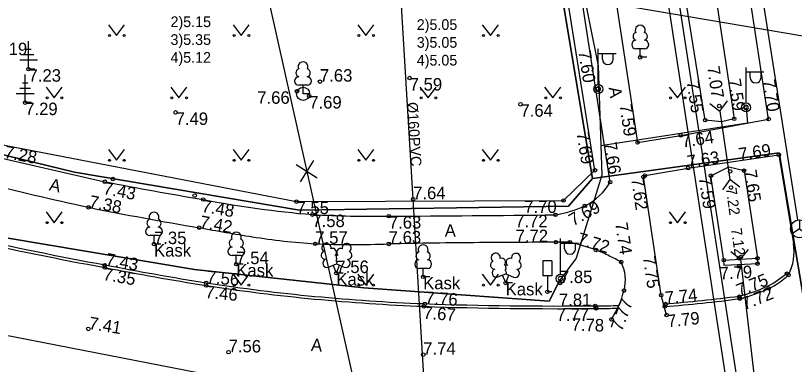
# Model space of a CAD drawing. Extents: x 473307 to 473719, y 6532843 to 6533381.
# Drawn here: x 473621.77 to 473665.5, y 6532915.94 to 6532935.52 of the extents above; entities that cross this region are included whole.
import ezdxf

# ---------------------------------------------------------------- set-up
doc = ezdxf.new("R2010")
doc.units = 0
for name, color, linetype in [('AED', 7, 'Continuous'), ('Default', 7, 'Continuous'), ('HALJASTUS', 7, 'Continuous'), ('KKAEV_NR', 7, 'Continuous'), ('KORGUS', 7, 'Continuous'), ('KTRASS', 7, 'Continuous'), ('KTRASS_TEKST', 7, 'Continuous'), ('LIIKLUS', 7, 'Continuous'), ('MPKAABEL', 7, 'Continuous'), ('PIIR', 7, 'Continuous'), ('POST', 7, 'Continuous'), ('PUU', 7, 'Continuous'), ('RAJATIS', 7, 'Continuous'), ('SIKAEV', 7, 'Continuous'), ('SITRASS', 7, 'Continuous'), ('TEE', 7, 'Continuous'), ('TRUUP', 7, 'Continuous'), ('TTRASS', 7, 'Continuous'), ('VEEKOGU', 7, 'Continuous'), ('VTRASS', 7, 'Continuous')]:
    doc.layers.add(name, color=color, linetype=linetype)

# ---------------------------------------------------------------- blocks, each defined once
blk = doc.blocks.new('SIKAEV')
at = {"layer": 'Default'}
for p, q in [((0, 1), (0, 0)), ((0, 0), (-0.83, -0.55)), ((0, 0), (0.83, -0.55))]:
    blk.add_line(p, q, dxfattribs=at)
blk.add_circle((0, 0), 1, dxfattribs=at)
blk = doc.blocks.new('LEHTP1')
at = {"layer": 'Default'}
for p, q in [((0.48, 0.95), (-0.48, 0.95)), ((0, 0), (0, 0.95)), ((0.76, 0), (0, 0))]:
    blk.add_line(p, q, dxfattribs=at)
for centre, radius, start, end in [((0, 3.04), 0.554, 332.5799, 207.4201), ((-0.34, 2.345), 0.465, 109.02174, 253.14154), ((0.34, 2.345), 0.465, 286.85082, 70.98591), ((-0.475, 1.425), 0.475, 90.0016, 269.3953), ((0.475, 1.425), 0.475, 270.6047, 89.9984)]:
    blk.add_arc(centre, radius, start, end, dxfattribs=at)
blk = doc.blocks.new('LEHTP2')
at = {"layer": 'Default'}
for p, q in [((-0.88, 0.67), (0.01, 1.02)), ((0, 0), (-0.35, 0.88)), ((0, 0), (0.36, 0.88)), ((0.01, 1.02), (0.89, 0.66)), ((0.76, 0), (0, 0))]:
    blk.add_line(p, q, dxfattribs=at)
blk.add_lwpolyline([(0.01, 2.01), (-0.03, 1.86), (-0.03, 1.82), (-0.01, 1.76), (0.03, 1.69), (0.04, 1.65), (0.01, 1.58), (-0.04, 1.48), (-0.05, 1.43), (-0.04, 1.4), (-0.02, 1.34), (0.05, 1.22), (0.06, 1.18), (0.05, 1.14), (0.02, 1.07), (0.01, 1.02)], dxfattribs=at)
for centre, radius, start, end in [((-1.114, 2.828), 0.512, 111.50269, 232.51731), ((-1.114, 2.828), 0.512, 350.48556, 111.50017), ((-0.445, 2.327), 0.448, 308.50412, 111.57247), ((0.481, 2.318), 0.45, 67.7016, 230.51262), ((1.158, 2.811), 0.512, 67.6168, 188.63142), ((1.158, 2.811), 0.512, 306.59966, 67.61428), ((-1.262, 2.005), 0.448, 111.43041, 274.49868), ((0.008, 1.535), 0.475, 66.76552, 111.50149), ((1.293, 1.986), 0.448, 264.6183, 67.68657), ((-1.053, 1.117), 0.475, 111.50143, 291.50036), ((1.07, 1.101), 0.475, 247.61661, 67.61554)]:
    blk.add_arc(centre, radius, start, end, dxfattribs=at)
blk = doc.blocks.new('LIIKLM')
at = {"layer": 'Default'}
for points in [[(-0.5, 3.5), (-0.5, 1.8)], [(0.5, 3.5), (-0.5, 3.5)], [(0.5, 3.5), (0.5, 1.8)], [(0.5, 1.8), (-0.5, 1.8)], [(0, 1.8), (0, 0)], [(0.5, 0), (0, 0)]]:
    blk.add_lwpolyline(points, dxfattribs=at)
blk = doc.blocks.new('MEPOST')
at = {"layer": 'Default'}
blk.add_circle((0, 0), 0.5, dxfattribs=at)
for start, end in [(0, 180), (180, 0)]:
    blk.add_arc((0, 0), 0.25, start, end, dxfattribs=at)
blk = doc.blocks.new('VAPOST')
at = {"layer": 'Default'}
for p, q in [((0, 0.5), (0, 4.5)), ((0, 4), (2, 4)), ((0.453, 3.358), (0.453, 4)), ((1.679, 3.358), (1.679, 4))]:
    blk.add_line(p, q, dxfattribs=at)
blk.add_arc((1.066, 3.358), 0.613, 180, 0, dxfattribs=at)
blk = doc.blocks.new('OKASP1')
at = {"layer": 'Default'}
for p, q in [((0, 0), (0, 3.15)), ((0.3, 2.2), (-0.3, 2.2)), ((1, 1), (-1, 1)), ((0.6, 1.6), (-0.6, 1.6)), ((0.72, 0), (0, 0))]:
    blk.add_line(p, q, dxfattribs=at)
blk = doc.blocks.new('MURU')
at = {"layer": 'Default'}
for p, q in [((-0.927, 1.213), (0, 0)), ((0, 0), (0.891, 1.213))]:
    blk.add_line(p, q, dxfattribs=at)
for centre in [(-0.802, 0), (0.856, 0)]:
    blk.add_circle(centre, 0.11, dxfattribs=at)
blk = doc.blocks.new('EITOOT')
at = {"layer": 'Default'}
for p, q in [((-0.99, 0.99), (0.99, -0.99)), ((-0.99, -0.99), (0.99, 0.99))]:
    blk.add_line(p, q, dxfattribs=at)
blk = doc.blocks.new('TORVAL')
at = {"layer": 'Default'}
blk.add_lwpolyline([(-1, -1), (0, 0), (-1, 1)], dxfattribs=at)

msp = doc.modelspace()

# ---------------------------------------------------------------- linework, layer by layer
at = {"layer": 'AED'}
msp.add_lwpolyline([(473550.051, 6532959.211), (473554.174, 6532956.453), (473573.719, 6532945.513), (473580.254, 6532941.8), (473591.86, 6532937.524), (473605.919, 6532932.298), (473608.286, 6532931.42), (473621.231, 6532928.229), (473637.541, 6532925.082), (473652.528, 6532925.143), (473654.3, 6532926.84), (473651.933, 6532941.676), (473648.983, 6532959.55), (473630.652, 6532956.493)], dxfattribs=at)
at = {"layer": 'KORGUS'}
for centre in [(473656.84, 6532933.183), (473622.495, 6532932.512), (473643.896, 6532932.015), (473638.856, 6532931.815), (473637.569, 6532931.272), (473654.406, 6532931.412), (473622.306, 6532930.636), (473638.254, 6532931.002), (473650.115, 6532930.547), (473661.278, 6532930.447), (473662.786, 6532930.367), (473630.752, 6532930.086), (473660.488, 6532929.653), (473662.113, 6532929.725), (473664.051, 6532929.713), (473659.115, 6532928.801), (473656.694, 6532928.4), (473664.624, 6532927.707), (473654.3, 6532926.84), (473659.529, 6532926.963), (473661.889, 6532926.777), (473662.671, 6532926.822), (473627.227, 6532926.347), (473657.021, 6532926.469), (473657.108, 6532926.542), (473660.81, 6532926.535), (473626.78, 6532926.195), (473655.15, 6532926.171), (473661.941, 6532925.868), (473631.824, 6532925.426), (473632.3, 6532925.198), (473637.541, 6532925.082), (473644.089, 6532925.217), (473652.528, 6532925.143), (473625.857, 6532924.763), (473653.731, 6532924.844), (473638.43, 6532924.353), (473642.723, 6532924.263), (473652.085, 6532924.341), (473632.077, 6532923.618), (473652.109, 6532922.805), (473652.89, 6532922.804), (473629.538, 6532922.697), (473638.594, 6532922.713), (473642.725, 6532922.707), (473654.351, 6532922.366), (473662.384, 6532921.899), (473662.478, 6532921.967), (473663.425, 6532921.898), (473626.769, 6532921.515), (473634.159, 6532921.573), (473655.768, 6532921.691), (473661.533, 6532921.794), (473662.397, 6532921.44), (473663.426, 6532921.599), (473626.768, 6532921.383), (473639.78, 6532921.07), (473665.08, 6532921.039), (473644.652, 6532920.859), (473665.165, 6532920.963), (473632.459, 6532920.372), (473632.464, 6532920.52), (473649.285, 6532920.518), (473652.332, 6532920.511), (473664.055, 6532920.206), (473651.628, 6532920.016), (473655.931, 6532920.094), (473658.014, 6532919.832), (473662.406, 6532919.746), (473644.749, 6532919.345), (473658.267, 6532919.331), (473662.432, 6532919.632), (473644.689, 6532919.206), (473654.309, 6532919.222), (473654.373, 6532919.087), (473658.22, 6532919.195), (473655.232, 6532918.473), (473658.322, 6532918.714), (473625.848, 6532917.937), (473633.723, 6532916.634), (473644.657, 6532916.492)]:
    msp.add_circle(centre, 0.1, dxfattribs=at)
at = {"layer": 'KTRASS'}
for points in [[(473635.219, 6532939.769), (473642.126, 6532908.847)], [(473643.308, 6532937.963), (473645.038, 6532909.078)], [(473654.386, 6532936.344), (473678.328, 6532932.291)]]:
    msp.add_lwpolyline(points, dxfattribs=at)
at = {"layer": 'MPKAABEL'}
for points in [[(473647.086, 6532975.076), (473649.618, 6532958.912), (473652.026, 6532944.888), (473654.472, 6532932.695), (473654.676, 6532926.56), (473653.253, 6532921.9), (473652.318, 6532920.677), (473651.722, 6532919.499), (473641.323, 6532920.251), (473631.817, 6532921.274), (473621.345, 6532923.026), (473612.93, 6532925.228), (473612.182, 6532926.232), (473611.163, 6532925.494), (473601.042, 6532928.37), (473592.161, 6532931.655), (473583.871, 6532934.989)], [(473649.618, 6532958.912), (473652.026, 6532944.888), (473654.472, 6532932.695), (473654.676, 6532926.56)], [(473662.786, 6532930.367), (473662.866, 6532929.486), (473654.621, 6532928.203)], [(473654.676, 6532926.56), (473653.253, 6532921.9), (473652.318, 6532920.677)], [(473612.182, 6532926.232), (473612.93, 6532925.228), (473621.345, 6532923.026), (473631.817, 6532921.274), (473641.323, 6532920.251), (473651.722, 6532919.499), (473652.318, 6532920.677)]]:
    msp.add_lwpolyline(points, dxfattribs=at)
at = {"layer": 'PIIR'}
for points in [[(473678.608, 6532842.593), (473677.66, 6532847.73), (473668.24, 6532906.4), (473664.64, 6532927.81), (473654.16, 6532926.37), (473630.89, 6533065.72), (473641.36, 6533067.51), (473636.3, 6533097.55), (473618.8, 6533170.64), (473609.94, 6533222.84), (473601.54, 6533272.81), (473599.09, 6533295.91), (473592.3, 6533328.43), (473587.14, 6533353.72), (473584.47, 6533353.28), (473580.56, 6533374.06), (473585.23, 6533374.14), (473584.699, 6533380.885)], [(473455.33, 6533045.76), (473478.82, 6533017), (473486.57, 6533007.64), (473509.62, 6532987.09), (473531.51, 6532970.21), (473554.34, 6532955.84), (473579.04, 6532941.93), (473607.63, 6532930.98), (473625.07, 6532926.73), (473637.7, 6532924.6), (473652.82, 6532924.82), (473654.16, 6532926.37), (473664.64, 6532927.81), (473668.24, 6532906.4), (473641.69, 6532906.33), (473620.6, 6532909.02), (473600.1, 6532914.5), (473579.89, 6532922.16), (473559.95, 6532931.3), (473540.88, 6532942.28), (473521.95, 6532954.78), (473501.05, 6532969.5), (473492.55, 6532977.62), (473473.12, 6532997.79)]]:
    msp.add_lwpolyline(points, dxfattribs=at)
msp.add_lwpolyline([(473486.57, 6533007.64), (473478.82, 6533017), (473548.5, 6533028.91), (473572.63, 6533056.43), (473618.6, 6533063.82), (473630.89, 6533065.72), (473654.16, 6532926.37), (473652.82, 6532924.82), (473637.7, 6532924.6), (473625.07, 6532926.73), (473607.63, 6532930.98), (473579.04, 6532941.93), (473554.34, 6532955.84), (473531.51, 6532970.21), (473509.62, 6532987.09)], close=True, dxfattribs=at)
at = {"layer": 'PUU'}
msp.add_circle((473637.909, 6532931.133), 0.37, dxfattribs=at)
at = {"layer": 'RAJATIS'}
msp.add_lwpolyline([(473661.533, 6532921.794), (473663.425, 6532921.898), (473663.441, 6532921.598), (473661.549, 6532921.494), (473661.533, 6532921.794)], dxfattribs=at)
at = {"layer": 'SITRASS'}
msp.add_lwpolyline([(473665.7, 6532924.051), (473655.633, 6532987.636)], dxfattribs=at)
at = {"layer": 'TEE'}
for points in [[(473655.15, 6532926.171), (473652.743, 6532941.812), (473649.742, 6532959.844), (473648.602, 6532966.274)], [(473650.702, 6532965.596), (473651.721, 6532959.945), (473654.578, 6532942.297), (473656.694, 6532928.4), (473659.115, 6532928.801), (473664.051, 6532929.713)], [(473664.051, 6532929.713), (473658.929, 6532963.29)], [(473620.072, 6532927.718), (473626.78, 6532926.195)], [(473658.322, 6532918.714), (473658.014, 6532919.832), (473657.021, 6532926.469), (473657.108, 6532926.542), (473659.529, 6532926.963), (473664.624, 6532927.707)], [(473664.624, 6532927.707), (473665.443, 6532922.736)]]:
    msp.add_lwpolyline(points, dxfattribs=at)
for centre, radius, start, end in [((473666.197, 6533109.975), 189.554, 255.83389, 257.71252), ((473672.107, 6533161.375), 239.509, 259.09089, 260.4328), ((473652.296, 6532927.8), 3.286, 295.887, 330.2753), ((473643.298, 6532982.324), 58.175, 259.10278, 265.20009), ((473664.625, 6533117.894), 196.984, 258.64973, 260.48939), ((473651.09, 6532930.543), 6.281, 279.1181, 294.8671), ((473641.858, 6532985.425), 61.168, 266.78753, 270.81048), ((473634.158, 6534514.158), 1589.918, 270.308657, 270.646047), ((473658.562, 6533069.406), 148.174, 259.70354, 260.87364), ((473665.577, 6533132.48), 214.635, 257.48495, 259.58307), ((473665.577, 6533132.48), 214.485, 257.48512, 259.58328), ((473640.718, 6532957.77), 35.121, 260.728, 266.5323), ((473640.739, 6532977.441), 54.77, 267.7555, 272.078), ((473650.136, 6532575.732), 347.054, 90.38346, 91.22362), ((473676.979, 6528564.969), 4357.907, 90.326986, 90.383462), ((473652.428, 6532866.919), 55.887, 89.5263, 90.327), ((473649.785, 6532909.791), 13.378, 70.0437, 76.5794), ((473662.614, 6532922.271), 2.866, 332.857, 9.3519), ((473650.992, 6532913.775), 9.224, 63.4385, 68.6471), ((473641.862, 6532895.44), 29.707, 62.0888, 63.5005), ((473653.767, 6532920.68), 2.242, 344.8537, 26.8019), ((473661.123, 6533098.234), 180.157, 259.00666, 260.84491), ((473661.123, 6533098.234), 180.007, 259.00642, 260.84472), ((473662.299, 6532923.974), 4.007, 294.9928, 313.5938), ((473662.299, 6532923.974), 4.157, 294.9928, 313.5938), ((473648.81, 6533027.186), 108.059, 261.29673, 267.81422), ((473648.81, 6533027.186), 107.909, 261.29704, 267.81416), ((473660.272, 6532928.322), 8.805, 284.0155, 294.9928), ((473650.212, 6532921.599), 5.914, 328.0897, 345.2574), ((473660.272, 6532928.322), 8.955, 283.9611, 294.9928), ((473651.967, 6533117.392), 198.17, 267.89687, 270.6954), ((473652.677, 6532993.137), 73.999, 274.28802, 277.55307), ((473652.677, 6532993.137), 74.149, 274.28704, 277.55959), ((473651.967, 6533117.392), 198.32, 267.89684, 270.69509), ((473654.486, 6532983.614), 64.377, 269.8983, 271.02487), ((473654.486, 6532983.614), 64.527, 269.89922, 270.96204), ((473654.486, 6532983.614), 64.377, 273.26159, 273.31582), ((473654.486, 6532983.614), 64.527, 273.29024, 273.31695)]:
    msp.add_arc(centre, radius, start, end, dxfattribs=at)
at = {"layer": 'TRUUP'}
for points in [[(473661.319, 6532930.166), (473661.876, 6532926.316)], [(473662.479, 6532921.846), (473663.659, 6532911.712)]]:
    msp.add_lwpolyline(points, dxfattribs=at)
at = {"layer": 'TTRASS'}
for points in [[(473670.739, 6532903.73), (473669.823, 6532910.623), (473662.59, 6532909.156), (473646.821, 6533011.679), (473633.537, 6533100.476), (473633.406, 6533101.178), (473632.559, 6533105.696), (473632.32, 6533106.603), (473631.402, 6533106.697), (473628.136, 6533106.491), (473627.343, 6533106.38), (473626.399, 6533106.377), (473626.238, 6533107.261), (473626.052, 6533109.168), (473625.777, 6533111.724), (473625.749, 6533112.421), (473625.73, 6533112.829)], [(473671.344, 6532903.733), (473670.333, 6532911.339), (473663.087, 6532909.869), (473647.414, 6533011.77), (473634.242, 6533098.966), (473634.072, 6533100.094), (473632.984, 6533106.198), (473632.738, 6533107.055), (473631.832, 6533107.173), (473627.702, 6533106.877), (473626.788, 6533106.911), (473626.656, 6533107.813), (473626.548, 6533108.653), (473626.413, 6533111.755), (473626.375, 6533112.253)]]:
    msp.add_lwpolyline(points, dxfattribs=at)
at = {"layer": 'VEEKOGU'}
msp.add_lwpolyline([(473656.06, 6532963.946), (473656.98, 6532963.798), (473662.113, 6532929.725), (473661.406, 6532929.565), (473660.488, 6532929.653), (473655.033, 6532963.521)], close=True, dxfattribs=at)
msp.add_lwpolyline([(473661.533, 6532921.794), (473660.81, 6532926.535), (473661.818, 6532927.029), (473662.671, 6532926.822), (473663.425, 6532921.898)], dxfattribs=at)
at = {"layer": 'VTRASS'}
msp.add_lwpolyline([(473503.731, 6532976.927), (473535.265, 6532954.21), (473555.891, 6532941.175), (473565.122, 6532936.508), (473600.672, 6532921.587), (473636.512, 6532914.617), (473674.923, 6532915.363), (473675.557, 6532915.427)], dxfattribs=at)

# ---------------------------------------------------------------- block references
at = {"layer": 'HALJASTUS', "xscale": 0.5, "yscale": 0.5}
for p in [(473627.438, 6532934.399), (473634.438, 6532934.399), (473641.438, 6532934.399), (473648.438, 6532934.399), (473623.938, 6532930.899), (473630.938, 6532930.899), (473644.938, 6532930.899), (473651.938, 6532930.899), (473658.938, 6532930.899), (473627.438, 6532927.399), (473634.438, 6532927.399), (473641.438, 6532927.399), (473648.438, 6532927.399), (473623.938, 6532923.899), (473658.938, 6532923.899), (473634.438, 6532920.399), (473641.438, 6532920.399), (473648.438, 6532920.399)]:
    msp.add_blockref('MURU', p, dxfattribs=at)
at = {"layer": 'KTRASS', "xscale": 0.5000000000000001, "yscale": 0.4999999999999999, "rotation": -77.40918596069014}
msp.add_blockref('EITOOT', (473638.118, 6532926.789), dxfattribs=at)
at = {"layer": 'LIIKLUS', "xscale": 0.5, "yscale": 0.5}
msp.add_blockref('LIIKLM', (473651.628, 6532920.016), dxfattribs=at)
at = {"layer": 'POST', "xscale": 0.5, "yscale": 0.5}
for name, p in [('VAPOST', (473654.488, 6532931.401)), ('VAPOST', (473662.786, 6532930.367)), ('MEPOST', (473654.488, 6532931.401)), ('MEPOST', (473662.786, 6532930.367)), ('VAPOST', (473652.367, 6532920.758)), ('MEPOST', (473652.367, 6532920.758))]:
    msp.add_blockref(name, p, dxfattribs=at)
at = {"layer": 'PUU', "xscale": 0.5, "yscale": 0.5}
for name, p in [('LEHTP1', (473656.84, 6532933.183)), ('OKASP1', (473622.495, 6532932.512)), ('LEHTP1', (473637.909, 6532931.133)), ('OKASP1', (473622.306, 6532930.636)), ('LEHTP1', (473629.538, 6532922.697)), ('LEHTP1', (473634.159, 6532921.573)), ('LEHTP2', (473639.78, 6532921.07)), ('LEHTP1', (473644.652, 6532920.859)), ('LEHTP2', (473649.285, 6532920.518))]:
    msp.add_blockref(name, p, dxfattribs=at)
at = {"layer": 'SIKAEV', "xscale": 0.5, "yscale": 0.5}
msp.add_blockref('SIKAEV', (473665.779, 6532923.557), dxfattribs=at)
at = {"layer": 'TRUUP'}
for p, xscale, yscale, rotation in [((473661.319, 6532930.166), 0.5000000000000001, 0.4999999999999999, -81.76131670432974), ((473661.876, 6532926.316), 0.49999999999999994, 0.5, 98.23868329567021), ((473662.479, 6532921.846), 0.49999999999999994, 0.5000000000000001, -83.35872919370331)]:
    msp.add_blockref('TORVAL', p, dxfattribs=dict(at, xscale=xscale, yscale=yscale, rotation=rotation))

# ---------------------------------------------------------------- texts
at = {"layer": 'KKAEV_NR'}
for s, p in [('2)5.15', (473630.465, 6532934.875)), ('2)5.05', (473644.293, 6532934.717)), ('3)5.35', (473630.465, 6532933.875)), ('3)5.05', (473644.293, 6532933.717)), ('4)5.12', (473630.465, 6532932.875)), ('4)5.05', (473644.293, 6532932.717))]:
    msp.add_text(s, height=0.6, dxfattribs=at).set_placement(p)
at = {"layer": 'KORGUS'}
for s, p in [('7.19', (473620.597, 6532933.301)), ('7.23', (473622.495, 6532931.812)), ('7.63', (473638.856, 6532931.815)), ('7.59', (473643.896, 6532931.315)), ('7.66', (473635.336, 6532930.572)), ('7.69', (473638.254, 6532930.302)), ('7.29', (473622.306, 6532929.936)), ('7.64', (473650.115, 6532929.847)), ('7.49', (473630.752, 6532929.386)), ('7.64', (473644.089, 6532925.217)), ('7.55', (473637.541, 6532924.382)), ('7.70', (473650.328, 6532924.443)), ('7.58', (473638.43, 6532923.653)), ('7.72', (473649.818, 6532923.641)), ('7.57', (473638.594, 6532922.713)), ('7.72', (473649.842, 6532922.805)), ('7.85', (473652.332, 6532920.511)), ('7.81', (473652.276, 6532919.222)), ('7.77', (473652.14, 6532918.387)), ('7.74', (473644.657, 6532916.492))]:
    msp.add_text(s, height=0.7, dxfattribs=at).set_placement(p)
for s, height, rotation, p in [('7.60', 0.7, 279.0648, (473653.363, 6532933.507)), ('7.07', 0.7, 278.567, (473660.594, 6532932.636)), ('7.55', 0.7, 279.1498, (473659.431, 6532931.812)), ('7.59', 0.7, 278.567, (473661.78, 6532931.933)), ('7.70', 0.7, 278.6727, (473663.719, 6532931.888)), ('7.59', 0.7, 278.6575, (473655.666, 6532930.503)), ('7.69', 0.7, 279.0648, (473653.257, 6532928.935)), ('7.64', 0.7, 8.5741, (473659.219, 6532928.109)), ('7.28', 0.7, 349.079, (473621.098, 6532927.542)), ('7.66', 0.7, 278.7486, (473654.81, 6532928.378)), ('7.69', 0.7, 8.3079, (473662.414, 6532927.384)), ('7.63', 0.7, 8.734, (473659.529, 6532926.963)), ('7.65', 0.7, 278.7059, (473662.671, 6532926.822)), ('7.62', 0.7, 278.5092, (473656.329, 6532926.365)), ('7.59', 0.7, 278.6708, (473660.118, 6532926.429)), ('7.43', 0.7, 349.3143, (473626.65, 6532925.507)), ('7.22', 0.6, 278, (473661.644, 6532925.826)), ('7.38', 0.7, 348.9186, (473625.857, 6532924.763)), ('7.48', 0.7, 350.3254, (473632.182, 6532924.508)), ('7.69', 0.7, 28.7068, (473653.073, 6532923.686)), ('7.42', 0.7, 350.0322, (473632.077, 6532923.618)), ('7.63', 0.7, 0.337, (473642.727, 6532923.563)), ('7.74', 0.7, 279, (473655.424, 6532923.864)), ('7.35', 0.7, 0.04, (473629.538, 6532922.697)), ('7.63', 0.7, 0.9928, (473642.725, 6532922.707)), ('7.72', 0.7, 343.3116, (473653.249, 6532922.696)), ('7.12', 0.6, 277.9486, (473661.937, 6532923.559)), ('7.43', 0.7, 349.9658, (473626.792, 6532921.512)), ('7.54', 0.7, 0.04, (473634.159, 6532921.573)), ('7.75', 0.7, 278.5092, (473656.986, 6532921.97)), ('7.56', 0.7, 0.04, (473639.78, 6532921.07)), ('7.35', 0.7, 349.9658, (473626.647, 6532920.693)), ('7.56', 0.7, 354.5955, (473632.478, 6532920.519)), ('7.79', 0.7, 3.1463, (473661.324, 6532920.703)), ('7.75', 0.7, 21.8592, (473662.406, 6532919.746)), ('7.46', 0.7, 354.5955, (473632.393, 6532919.675)), ('7.72', 0.7, 21.8592, (473662.693, 6532918.982)), ('7.76', 0.7, 356.1848, (473644.749, 6532919.345)), ('7.74', 0.7, 5.6381, (473658.267, 6532919.331)), ('7.77', 0.7, 69.7373, (473655.814, 6532917.756)), ('7.67', 0.7, 356, (473644.64, 6532918.508)), ('7.41', 0.7, 350.6413, (473625.848, 6532917.937)), ('7.78', 0.7, 358.2869, (473652.979, 6532917.84)), ('7.79', 0.7, 6.233, (473658.398, 6532918.018)), ('7.56', 0.7, 359.2984, (473633.723, 6532916.634))]:
    msp.add_text(s, height=height, rotation=rotation, dxfattribs=at).set_placement(p)
at = {"layer": 'KTRASS_TEKST'}
msp.add_text('%%C160PVC', height=0.6, rotation=273.5133, dxfattribs=at).set_placement((473643.743, 6532930.648))
at = {"layer": 'PUU'}
for p in [(473629.538, 6532921.997), (473634.159, 6532920.873), (473639.78, 6532920.37), (473644.652, 6532920.159), (473649.285, 6532919.818)]:
    msp.add_text('Kask', height=0.7, dxfattribs=at).set_placement(p)
at = {"layer": 'TEE'}
for rotation, p in [(278.6575, (473655.064, 6532931.477)), (347.9858, (473623.612, 6532925.718)), (355.8838, (473638.337, 6532916.708))]:
    msp.add_text('A', height=0.7, rotation=rotation, dxfattribs=at).set_placement(p)
msp.add_text('A', height=0.7, dxfattribs=at).set_placement((473645.863, 6532923.108))

doc.saveas('drawing.dxf')
